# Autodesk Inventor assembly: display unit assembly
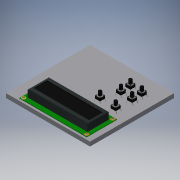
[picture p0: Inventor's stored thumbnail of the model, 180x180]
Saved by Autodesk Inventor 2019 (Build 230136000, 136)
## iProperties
Created: 2020-02
Part Number: display unit assembly
Document SubType Name: Assembly
Designer: Tanvi P Heblikar
Author: Tanvi P Heblikar
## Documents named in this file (4)
- C:\Users\Tanvi P Heblikar\Documents\display unit assembly.iam
- C:\Users\Tanvi P Heblikar\Desktop\exploration\16x2-lcd.snapshot.2\LCD.ipt
- C:\Users\Tanvi P Heblikar\Desktop\exploration\push-button-6x6mm-1.snapshot.2\6x6 mm.ipt
- C:\Users\Tanvi P Heblikar\Documents\base.ipt
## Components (8 placed, 3 different names)
1. LCD:1
2. base:1
3. 6x6 mm:1
4. 6x6 mm:3
5. 6x6 mm:4
6. 6x6 mm:5
7. 6x6 mm:6
8. 6x6 mm:7
